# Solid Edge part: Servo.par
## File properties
Author: wojci
Template: ISO Metric Part.par
Last saved by: wojci
Revision: 4
Application: Solid Edge
Username: wojci
Accuracy: 0.990
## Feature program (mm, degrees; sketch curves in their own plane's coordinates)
sketch for "unnamed Protrusion 1" plane through (0, 0, 0) normal (0, 0, 1) x-axis (1, 0, 0)
  line (10, -18.25) -> (10, 18.25)
  line (10, 18.25) -> (-10, 18.25)
  line (-10, 18.25) -> (-10, -18.25)
  line (-10, -18.25) -> (10, -18.25)
extrude "unnamed Protrusion 1" add finite 40 along +normal
sketch for "ExtrudedProtrusion_2" plane through (0, 0, 40) normal (0, 0, 1) x-axis (0, 1, 0)
  line (7.75, -10) -> (7.75, 10)
  line (7.75, 10) -> (13.25, 10)
  line (13.25, 10) -> (13.25, -10)
  line (13.25, -10) -> (7.75, -10)
extrude "ExtrudedProtrusion_2" add finite 7 along +normal
sketch for "ExtrudedProtrusion_3" plane through (0, 0, 0) normal (0, 0, -1) x-axis (0, 1, 0)
  line (7.75, -10) -> (7.75, 10)
  line (7.75, 10) -> (13.25, 10)
  line (13.25, 10) -> (13.25, -10)
  line (13.25, -10) -> (7.75, -10)
extrude "ExtrudedProtrusion_3" add finite 7 along +normal
sketch for "ExtrudedProtrusion_4" plane through (0, 18.25, 20) normal (0, 1, 0) x-axis (-1, 0, 0)
  circle centre (0.3897, 10) radius 6
extrude "ExtrudedProtrusion_4" add finite 12 along +normal
sketch for "ExtrudedProtrusion_5" plane through (0, -5.25, 40) normal (0, 0, 1) x-axis (0, 1, 0)
  line (-7.5, -4) -> (-2.5, -4)
  line (-2.5, -4) -> (-2.5, 4)
  line (-2.5, 4) -> (-7.5, 4)
  line (-7.5, 4) -> (-7.5, -4)
extrude "ExtrudedProtrusion_5" add finite 1.5 along +normal
sketch for "Hole_1" plane through (0, 13.25, 43.5) normal (0, 1, 0) x-axis (-1, 0, 0)
  hole centre (-5, 0.75) bore radius 1.25
hole "Hole_1" diameter 2.5 through
sketch for "unnamed Hole 1" plane through (0, 13.25, 43.5) normal (0, 1, 0) x-axis (-1, 0, 0)
  hole centre (5, 0.75) bore radius 1.25
hole "unnamed Hole 1" through
sketch for "unnamed Hole 2" plane through (0, 13.25, 43.5) normal (0, 1, 0) x-axis (-1, 0, 0)
  hole centre (-5, -47.75) bore radius 1.25
hole "unnamed Hole 2" through
sketch for "unnamed Hole 3" plane through (0, 13.25, 43.5) normal (0, 1, 0) x-axis (-1, 0, 0)
  hole centre (5, -47.75) bore radius 1.25
hole "unnamed Hole 3" through
pattern "unnamed Pattern 1" of "Hole_1", "unnamed Hole 1", "unnamed Hole 2", "unnamed Hole 3"
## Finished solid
Body 1: solid body, 25 faces, 58 edges, 32 vertices.
  Faces by surface: plane 20, cylinder 5
  Edges by curve: line 48, circle 10
Bounding box of the edges (mm): 20.000 x 48.500 x 54.000, from (-10, -18.25, -7) to (10, 30.25, 47).
Cylindrical faces by radius (mm): R1.25 x4, R6 x1
Planar faces by outward normal: +x 2, +y 5, +z 4, -x 2, -y 4, -z 3
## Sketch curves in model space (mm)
line (4, -7.75, 40) -> (-4, -7.75, 40)
line (-4, -7.75, 40) -> (-4, -12.75, 40)
line (-4, -12.75, 40) -> (4, -12.75, 40)
line (4, -12.75, 40) -> (4, -7.75, 40)
circle centre (-0.3897, 18.25, 30) radius 6
line (10, 13.25, 0) -> (-10, 13.25, 0)
line (-10, 13.25, 0) -> (-10, 7.75, 0)
line (-10, 7.75, 0) -> (10, 7.75, 0)
line (10, 7.75, 0) -> (10, 13.25, 0)
line (-10, 13.25, 40) -> (10, 13.25, 40)
line (10, 13.25, 40) -> (10, 7.75, 40)
line (10, 7.75, 40) -> (-10, 7.75, 40)
line (-10, 7.75, 40) -> (-10, 13.25, 40)
line (10, -18.25, 0) -> (10, 18.25, 0)
line (10, 18.25, 0) -> (-10, 18.25, 0)
line (-10, 18.25, 0) -> (-10, -18.25, 0)
line (-10, -18.25, 0) -> (10, -18.25, 0)
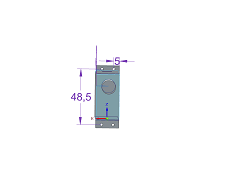
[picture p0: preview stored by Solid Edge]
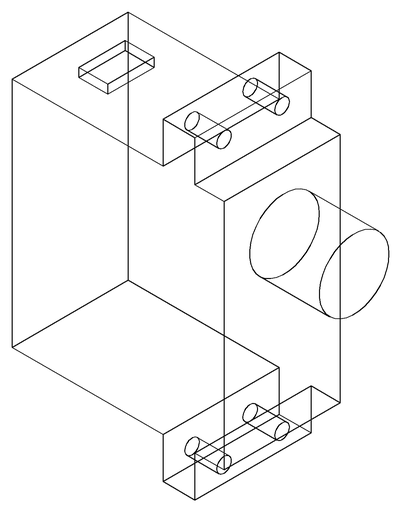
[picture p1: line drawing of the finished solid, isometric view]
